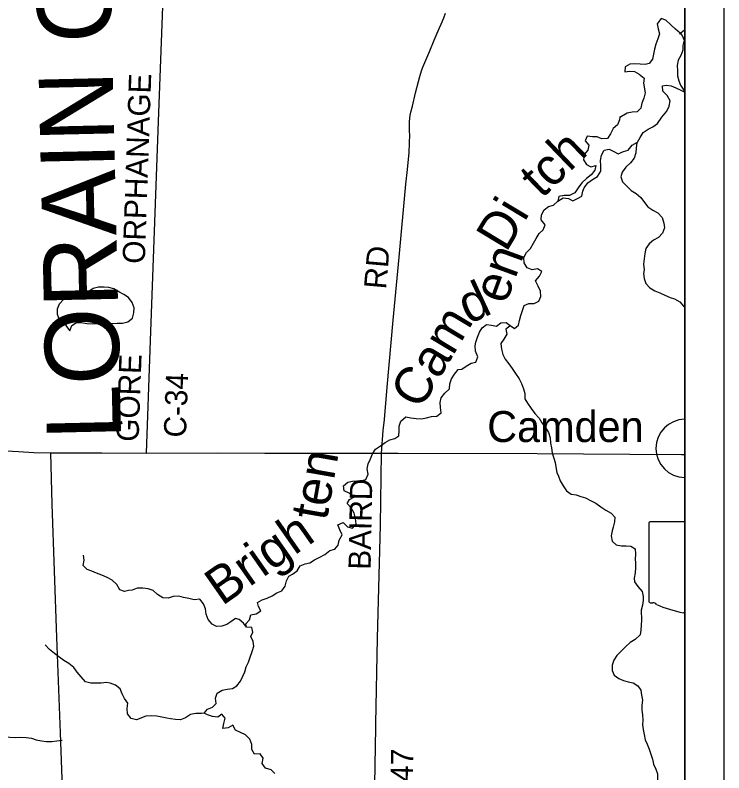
# Model space of a CAD drawing. Extents: x 0 to 34, y 0 to 22.
# Drawn here: x 7.191 to 9, y 16.386 to 18.319 of the extents above; entities that cross this region are included whole.
import ezdxf

# ---------------------------------------------------------------- set-up
doc = ezdxf.new("R2010")
doc.units = 0
for name, color, linetype in [('GM_X_Corporation', 7, 'Continuous'), ('GM_X_County_Road', 7, 'Continuous'), ('GM_X_County_Road_Text', 7, 'Continuous'), ('GM_X_County_Text', 7, 'Continuous'), ('GM_X_Minor_Lake', 7, 'Continuous'), ('GM_X_Minor_River', 7, 'Continuous'), ('GM_X_Minor_River_Text', 7, 'Continuous'), ('GM_X_State_Route', 7, 'Continuous'), ('GM_X_State_Shield', 7, 'Continuous'), ('GM_X_Township_Road', 7, 'Continuous'), ('GM_X_Township_Road_Text', 7, 'Continuous'), ('GM_X_Unincorporated', 7, 'Continuous'), ('GM_X_Unincorporated_Text', 7, 'Continuous'), ('SH_Data', 7, 'Continuous')]:
    doc.layers.add(name, color=color, linetype=linetype)

msp = doc.modelspace()

# ---------------------------------------------------------------- linework, layer by layer
at = {"layer": 'GM_X_Corporation'}
msp.add_lwpolyline([(8.9, 14.1), (8.9, 20.9), (6.9799, 20.9), (6.9799, 20.8943), (6.9814, 20.8368), (6.9837, 20.7502), (6.9864, 20.657), (6.9927, 20.4427), (6.9931, 20.4255), (6.9989, 19.9212), (7.0018, 19.871), (7.0046, 19.8599), (7.0077, 19.6756), (7.0107, 19.4664), (7.0305, 18.5559), (7.0429, 18.0629), (7.0494, 17.8247), (7.0577, 17.449), (7.0649, 17.2134), (7.0651, 17.204), (7.0717, 16.9849), (7.0838, 16.6084), (7.1072, 15.3824)], dxfattribs=at)
msp.add_lwpolyline([(8.9, 14.638), (8.9, 19.8484), (8.3424, 19.8533), (7.6795, 19.8561), (7.3272, 19.8568), (7.1717, 19.8568), (7.0046, 19.8599), (7.0077, 19.6756), (7.0107, 19.4664), (7.0305, 18.5559), (7.0429, 18.0629), (7.0494, 17.8247), (7.0577, 17.449), (7.0649, 17.2134), (7.0651, 17.204), (7.0717, 16.9849), (7.0838, 16.6084), (7.1072, 15.3824), (7.118, 14.8105), (7.1215, 14.6514), (7.384, 14.6494), (8.0793, 14.6442), (8.8452, 14.6384)], close=True, dxfattribs=at)
at = {"layer": 'GM_X_County_Road'}
for points in [[(7.5268, 17.2021), (7.5356, 17.4654), (7.5568, 18.0484), (7.58, 18.6579)], [(7.3381, 15.6814), (7.321, 16.1128), (7.3068, 16.488), (7.2978, 16.731), (7.2856, 17.0713), (7.2822, 17.2029)], [(7.2822, 17.2029), (7.4121, 17.2024), (7.5268, 17.2021)]]:
    msp.add_lwpolyline(points, dxfattribs=at)
at = {"layer": 'GM_X_Minor_Lake'}
for points in [[(8.8888, 18.2734), (8.8769, 18.2832), (8.865, 18.2944), (8.8523, 18.3064), (8.8401, 18.3105), (8.8299, 18.2971), (8.8324, 18.2845), (8.8359, 18.2717), (8.8319, 18.2587), (8.826, 18.2457), (8.8227, 18.2324), (8.8176, 18.2072), (8.809, 18.1961), (8.7995, 18.1933), (8.7862, 18.1939), (8.7725, 18.1949), (8.7603, 18.1944), (8.7483, 18.1874), (8.7469, 18.1745), (8.7594, 18.1765), (8.772, 18.1759), (8.7842, 18.1688), (8.7965, 18.1587), (8.7947, 18.1458), (8.7996, 18.1215), (8.7956, 18.1078), (8.7908, 18.0948), (8.7879, 18.0819), (8.7788, 18.0723), (8.7663, 18.0717), (8.7534, 18.0693), (8.7345, 18.0586)], [(8.8888, 18.2734), (8.8769, 18.2832), (8.865, 18.2944), (8.8523, 18.3064), (8.8401, 18.3105), (8.8299, 18.2971), (8.8324, 18.2845), (8.8359, 18.2717), (8.8319, 18.2587), (8.826, 18.2457), (8.8227, 18.2324), (8.8176, 18.2072), (8.809, 18.1961), (8.7995, 18.1933), (8.7862, 18.1939), (8.7725, 18.1949), (8.7603, 18.1944), (8.7483, 18.1874), (8.7469, 18.1745), (8.7594, 18.1765), (8.772, 18.1759), (8.7842, 18.1688), (8.7965, 18.1587), (8.7947, 18.1458), (8.7996, 18.1215), (8.7956, 18.1078), (8.7908, 18.0948), (8.7879, 18.0819), (8.7788, 18.0723), (8.7663, 18.0717), (8.7534, 18.0693), (8.7346, 18.0587)], [(8.8888, 18.2734), (8.8938, 18.2678), (8.8985, 18.2553), (8.8952, 18.2419), (8.895, 18.2298), (8.8906, 18.2164), (8.8835, 18.2042), (8.881, 18.1912), (8.8815, 18.1776), (8.8813, 18.1646), (8.8848, 18.1521), (8.8895, 18.1404), (8.8977, 18.1276), (8.9, 18.1275)], [(8.842, 18.0589), (8.8549, 18.0743), (8.8608, 18.0873), (8.8633, 18.101), (8.8552, 18.1142), (8.8444, 18.1258), (8.8431, 18.1387), (8.8526, 18.1408), (8.8652, 18.1386), (8.8774, 18.1338), (8.8904, 18.1279), (8.9, 18.1225)], [(8.7346, 18.0587), (8.7334, 18.0522), (8.7283, 18.0394), (8.7171, 18.0301), (8.7105, 18.0165), (8.7027, 18.0044), (8.689, 18.0035), (8.6765, 18.0086), (8.6647, 18.0092), (8.651, 18.0102), (8.6463, 17.9985), (8.6556, 17.9877), (8.6532, 17.9752), (8.6431, 17.9635), (8.6418, 17.9499), (8.6492, 17.938), (8.6606, 17.9325), (8.6732, 17.9361), (8.6707, 17.9239), (8.6614, 17.9123), (8.6491, 17.9026), (8.6372, 17.8914), (8.6279, 17.879), (8.6193, 17.8658), (8.6059, 17.8595), (8.5926, 17.8593), (8.5788, 17.8569), (8.5764, 17.8451), (8.5902, 17.8529), (8.6039, 17.8519), (8.6144, 17.8453), (8.6267, 17.8512), (8.6375, 17.8575), (8.6399, 17.8704)], [(8.7346, 18.0587), (8.7334, 18.0522), (8.7283, 18.0394), (8.7171, 18.0301), (8.7105, 18.0165), (8.7027, 18.0044), (8.689, 18.0035), (8.6765, 18.0086), (8.6647, 18.0092), (8.651, 18.0102), (8.6463, 17.9985), (8.6556, 17.9877), (8.6532, 17.9752), (8.6431, 17.9635), (8.6418, 17.9499), (8.6492, 17.938), (8.6606, 17.9325), (8.6732, 17.9361), (8.6707, 17.9239), (8.6614, 17.9123), (8.6491, 17.9026), (8.6372, 17.8914), (8.6279, 17.879), (8.6193, 17.8658), (8.6059, 17.8595), (8.5926, 17.8593), (8.5788, 17.8569), (8.5764, 17.8451), (8.5902, 17.8529), (8.6039, 17.8519), (8.6144, 17.8453), (8.6267, 17.8512), (8.6375, 17.8575), (8.6399, 17.8704)], [(8.6399, 17.8704), (8.6431, 17.8787), (8.6531, 17.8911), (8.6651, 17.9004), (8.6774, 17.9079), (8.6859, 17.9214), (8.6861, 17.9351), (8.6848, 17.9481), (8.688, 17.9617), (8.6943, 17.9749), (8.7073, 17.9774), (8.719, 17.9711), (8.7307, 17.9652), (8.7437, 17.9715), (8.756, 17.9751), (8.7664, 17.9875), (8.7799, 17.9949), (8.7861, 18.0074), (8.7943, 18.0198), (8.807, 18.028), (8.8189, 18.0342), (8.8308, 18.0432), (8.842, 18.0589)], [(7.4557, 17.6134), (7.4432, 17.6212), (7.4303, 17.6245), (7.4182, 17.625), (7.4044, 17.6249), (7.3907, 17.622), (7.3792, 17.6142), (7.3654, 17.6106), (7.3529, 17.612), (7.3403, 17.6083), (7.3265, 17.6021), (7.3149, 17.5935), (7.3037, 17.5823), (7.2982, 17.5694), (7.2984, 17.5561), (7.3036, 17.5431), (7.316, 17.5353), (7.3227, 17.5246), (7.3306, 17.5138)], [(7.3306, 17.5138), (7.3357, 17.5278), (7.348, 17.5348), (7.3606, 17.535), (7.3742, 17.5322), (7.3879, 17.5316), (7.4016, 17.5329), (7.4154, 17.5346), (7.4291, 17.5336), (7.4386, 17.5327), (7.4515, 17.5333), (7.4656, 17.5334), (7.4786, 17.5367), (7.4909, 17.546), (7.4945, 17.5596), (7.4947, 17.5725), (7.49, 17.5863), (7.4802, 17.5986), (7.4685, 17.6064), (7.4557, 17.6134)]]:
    msp.add_lwpolyline(points, dxfattribs=at)
at = {"layer": 'GM_X_Minor_River'}
for points in [[(8.9, 18.2814), (8.8994, 18.2809), (8.8871, 18.2707)], [(8.7778, 17.9938), (8.7766, 17.9809), (8.7753, 17.968), (8.7709, 17.9547), (8.762, 17.9423), (8.75, 17.9315), (8.7407, 17.9191), (8.7371, 17.9066), (8.7415, 17.8943), (8.7524, 17.8828), (8.7637, 17.8716), (8.7761, 17.8645), (8.7882, 17.8537), (8.7979, 17.8414), (8.8061, 17.8299), (8.819, 17.8217), (8.8314, 17.8146), (8.8427, 17.8027), (8.8471, 17.7889), (8.8488, 17.7763), (8.8436, 17.7627), (8.8328, 17.7519), (8.8206, 17.7452), (8.8094, 17.7359), (8.8005, 17.7235), (8.7984, 17.7113), (8.7963, 17.6977), (8.7946, 17.684), (8.7963, 17.6699), (8.795, 17.6604), (8.7967, 17.6471), (8.8011, 17.6345), (8.8112, 17.6233), (8.8237, 17.6159), (8.8366, 17.6111), (8.8494, 17.6045), (8.8627, 17.5993), (8.8744, 17.5953), (8.8873, 17.5875), (8.8974, 17.5767), (8.9, 17.5738)], [(8.4821, 17.553), (8.4857, 17.5659), (8.4904, 17.5787), (8.5027, 17.5835), (8.516, 17.5837), (8.5275, 17.5896), (8.5326, 17.6017), (8.5324, 17.615), (8.5261, 17.6276), (8.5195, 17.641), (8.5299, 17.6534), (8.5358, 17.6651), (8.5245, 17.6718), (8.5107, 17.6693), (8.4978, 17.6744), (8.4904, 17.6875), (8.4891, 17.7012), (8.4961, 17.7133), (8.5069, 17.7241), (8.5139, 17.7373), (8.521, 17.7498), (8.5284, 17.7626), (8.5392, 17.7715), (8.5439, 17.784), (8.5338, 17.7967), (8.5348, 17.81), (8.5414, 17.8225), (8.5529, 17.831), (8.5655, 17.8343), (8.5764, 17.8451)], [(7.7819, 16.7574), (7.7801, 16.7658), (7.7894, 16.7763), (7.793, 16.7896), (7.806, 16.7921), (7.8186, 16.7995), (7.8127, 16.8102), (7.8098, 16.8209), (7.8221, 16.8272), (7.8343, 16.8316), (7.847, 16.8378), (7.8589, 16.8449), (7.8719, 16.8508), (7.8804, 16.8624), (7.8841, 16.8761), (7.8899, 16.8881), (7.8995, 16.8929), (7.9114, 16.9011), (7.9188, 16.9143), (7.9311, 16.9195), (7.9437, 16.9219), (7.9556, 16.9297), (7.969, 16.936), (7.9817, 16.943), (7.994, 16.9531), (8.0074, 16.9567), (8.0155, 16.9669), (8.018, 16.9801), (8.0258, 16.9929), (8.0203, 17.0059), (8.0151, 17.0186), (8.0281, 17.0245), (8.0398, 17.0133), (8.0519, 17.0104), (8.0612, 17.0217), (8.0602, 17.0346), (8.0566, 17.0484), (8.0488, 17.0618), (8.0387, 17.0734), (8.0446, 17.0835), (8.0557, 17.0895), (8.044, 17.0999), (8.0312, 17.1054), (8.0294, 17.1184), (8.0402, 17.1277), (8.0521, 17.1306), (8.0616, 17.1308), (8.0719, 17.1303), (8.086, 17.1346), (8.0919, 17.1478), (8.0898, 17.1616), (8.0926, 17.1745), (8.0982, 17.1869), (8.1037, 17.1998), (8.1111, 17.2122), (8.1237, 17.2208), (8.1357, 17.2289), (8.1472, 17.2356), (8.1606, 17.2388), (8.1709, 17.2455), (8.1715, 17.2584), (8.1716, 17.2702), (8.176, 17.2835), (8.188, 17.2943), (8.2009, 17.2922), (8.2146, 17.2905), (8.2283, 17.2891), (8.2409, 17.2916), (8.2539, 17.2952), (8.2676, 17.2961), (8.2787, 17.3047), (8.2766, 17.3184), (8.2757, 17.3306), (8.2785, 17.3428), (8.2882, 17.3544), (8.3001, 17.3656), (8.3007, 17.3782), (8.3051, 17.391), (8.3125, 17.4031), (8.3218, 17.4151), (8.3313, 17.4161), (8.3421, 17.4235), (8.3547, 17.4317), (8.3666, 17.4342), (8.3721, 17.4478), (8.3658, 17.4616), (8.3649, 17.4753), (8.3669, 17.4848), (8.3709, 17.498), (8.376, 17.5105), (8.383, 17.5218), (8.3946, 17.5296), (8.4071, 17.5287), (8.4196, 17.5254), (8.4312, 17.5344), (8.4441, 17.5353), (8.4543, 17.5272), (8.466, 17.5194), (8.4756, 17.528), (8.4788, 17.5401), (8.4821, 17.553)], [(8.4548, 17.5268), (8.4539, 17.526), (8.4435, 17.5178), (8.446, 17.5052), (8.4382, 17.4924), (8.4312, 17.4811), (8.4325, 17.4674), (8.4358, 17.4537), (8.4421, 17.4418), (8.4514, 17.4295), (8.4596, 17.4176), (8.4686, 17.4049), (8.4772, 17.3915), (8.4835, 17.3792), (8.489, 17.3662), (8.4923, 17.3543), (8.4921, 17.3407), (8.4991, 17.3291), (8.5081, 17.3157), (8.5174, 17.303), (8.5283, 17.2907), (8.5358, 17.2788), (8.5447, 17.2668), (8.5522, 17.2542), (8.5569, 17.2404), (8.5575, 17.2275), (8.5604, 17.2156), (8.5621, 17.2027), (8.5694, 17.1782), (8.5715, 17.1668), (8.574, 17.1527), (8.5777, 17.1431), (8.5821, 17.1313), (8.5895, 17.1182), (8.5981, 17.1056), (8.6101, 17.097), (8.6227, 17.0953), (8.6352, 17.0913), (8.6469, 17.0877), (8.6598, 17.081), (8.673, 17.0744), (8.6858, 17.0651), (8.6987, 17.0561), (8.7123, 17.0487), (8.7216, 17.0383), (8.7211, 17.0261), (8.7179, 17.0132), (8.7151, 17.0034), (8.7126, 16.9905), (8.7147, 16.9775), (8.7248, 16.9679), (8.7385, 16.9654), (8.7503, 16.9656), (8.7625, 16.9643), (8.7738, 16.9576), (8.7744, 16.9439), (8.7738, 16.9314), (8.7741, 16.9219), (8.7743, 16.9093), (8.7733, 16.896), (8.7713, 16.8831), (8.7719, 16.8736), (8.7801, 16.8613), (8.7913, 16.8486), (8.7942, 16.836), (8.7937, 16.8261), (8.792, 16.8136), (8.7888, 16.8011), (8.7899, 16.7752), (8.789, 16.7631), (8.7885, 16.7502), (8.7868, 16.738), (8.7737, 16.726), (8.7606, 16.7186), (8.7502, 16.7085), (8.7386, 16.6969), (8.727, 16.6857), (8.7196, 16.6736), (8.7153, 16.6611), (8.7147, 16.6475), (8.7198, 16.6352), (8.7323, 16.6263), (8.7436, 16.6215), (8.7554, 16.6183), (8.7683, 16.6155), (8.7808, 16.6084), (8.7878, 16.5969), (8.7896, 16.5843), (8.7921, 16.5718), (8.7911, 16.5588), (8.7906, 16.5455), (8.7923, 16.5337), (8.7929, 16.5204), (8.7927, 16.5086), (8.7937, 16.4964), (8.7966, 16.4838), (8.7994, 16.4705), (8.8046, 16.459), (8.8097, 16.4464), (8.8138, 16.4338), (8.8181, 16.4208)], [(7.7819, 16.7574), (7.774, 16.7675), (7.7628, 16.7775), (7.7533, 16.7796), (7.7417, 16.7717), (7.7314, 16.7647), (7.7187, 16.7603), (7.705, 16.759), (7.6937, 16.7652), (7.6836, 16.7772), (7.6788, 16.791), (7.6775, 16.8047), (7.6723, 16.8173), (7.6622, 16.8289), (7.6485, 16.8272), (7.6348, 16.8312), (7.6211, 16.8337), (7.6086, 16.8365), (7.5945, 16.836), (7.5819, 16.832), (7.5682, 16.8326), (7.5542, 16.8408), (7.5437, 16.8512), (7.5305, 16.8559), (7.5168, 16.8573), (7.5031, 16.8571), (7.49, 16.852), (7.4805, 16.851), (7.4706, 16.8485), (7.4588, 16.8532), (7.4506, 16.8663), (7.439, 16.8779), (7.4265, 16.8845), (7.4125, 16.8901), (7.3989, 16.8956), (7.3868, 16.9007), (7.375, 16.9047), (7.3649, 16.9147), (7.367, 16.9284), (7.366, 16.9417)], [(7.6825, 16.5342), (7.6738, 16.5382), (7.6823, 16.5483), (7.6949, 16.5534), (7.7046, 16.5628), (7.7029, 16.5765), (7.7065, 16.589), (7.7195, 16.5972), (7.7321, 16.5996), (7.7458, 16.6009), (7.7574, 16.6076), (7.7667, 16.6196), (7.7725, 16.6325), (7.7773, 16.6438), (7.7812, 16.6563), (7.7867, 16.6684), (7.7907, 16.6813), (7.7959, 16.6952), (7.8006, 16.7089), (7.7989, 16.7214), (7.7926, 16.7341), (7.7977, 16.745), (7.7956, 16.7565), (7.7819, 16.7574)], [(7.6738, 16.5382), (7.6665, 16.5375), (7.6528, 16.5373), (7.6391, 16.5345), (7.626, 16.5267), (7.613, 16.5212), (7.6008, 16.5221), (7.5879, 16.5239), (7.5784, 16.5255), (7.5655, 16.5284), (7.5526, 16.5309), (7.5389, 16.5315), (7.5252, 16.5309), (7.5007, 16.5214), (7.487, 16.525), (7.4777, 16.5366), (7.4771, 16.5499), (7.4788, 16.5635), (7.4702, 16.5755), (7.4647, 16.5877), (7.4591, 16.6007), (7.4471, 16.6093), (7.4335, 16.6148), (7.424, 16.6169), (7.411, 16.6151), (7.398, 16.615), (7.3843, 16.6152), (7.3711, 16.6184), (7.3598, 16.6308), (7.3493, 16.6427), (7.3407, 16.655), (7.3283, 16.6651), (7.3151, 16.6729), (7.303, 16.6818), (7.2914, 16.6907), (7.2793, 16.7008), (7.2677, 16.7124)], [(7.8544, 16.3844), (7.8446, 16.3937), (7.8306, 16.3981), (7.822, 16.41), (7.8241, 16.4237), (7.8162, 16.4345), (7.8025, 16.4339), (7.7955, 16.4458), (7.7953, 16.4587), (7.7905, 16.4717), (7.7792, 16.4829), (7.7664, 16.4892), (7.7535, 16.4947), (7.7472, 16.5074), (7.7346, 16.5011), (7.7212, 16.499), (7.7237, 16.5119), (7.7273, 16.5256), (7.719, 16.5359), (7.7087, 16.5277), (7.695, 16.5298), (7.6825, 16.5342)], [(7.0874, 16.4748), (7.098, 16.4746), (7.1118, 16.4782), (7.1255, 16.4792), (7.1384, 16.4774), (7.1513, 16.478), (7.1651, 16.4782), (7.178, 16.4772), (7.1917, 16.4766), (7.2054, 16.4768), (7.2191, 16.4758), (7.2328, 16.4741), (7.2453, 16.4705), (7.2582, 16.4676), (7.2711, 16.4663), (7.2848, 16.4657), (7.2974, 16.4678), (7.3111, 16.4695)], [(8.8181, 16.4208), (8.8203, 16.4082), (8.8265, 16.3952), (8.8306, 16.3833), (8.8304, 16.3738), (8.831, 16.3601), (8.8346, 16.3471), (8.8383, 16.3338), (8.8427, 16.3215), (8.847, 16.3089), (8.8503, 16.2967), (8.8517, 16.2849), (8.8519, 16.272), (8.8513, 16.2587), (8.853, 16.2457), (8.8517, 16.2328), (8.8515, 16.2187), (8.8529, 16.2062), (8.8565, 16.1943), (8.8605, 16.1813), (8.8634, 16.1714), (8.8666, 16.1577), (8.868, 16.1443)]]:
    msp.add_lwpolyline(points, dxfattribs=at)
at = {"layer": 'GM_X_State_Route'}
for points in [[(7.0651, 17.2128), (7.1374, 17.2097), (7.1995, 17.2057), (7.2392, 17.2038), (7.2822, 17.2029)], [(7.2822, 17.2029), (7.4121, 17.2024), (7.5268, 17.2021)], [(7.5268, 17.2021), (7.7067, 17.2029), (7.8287, 17.2021), (7.9773, 17.2015), (8.0999, 17.2015), (8.1263, 17.2015), (8.1689, 17.2014), (8.5239, 17.2008), (8.7597, 17.1993), (8.8917, 17.1982), (8.9, 17.1982)]]:
    msp.add_lwpolyline(points, dxfattribs=at)
at = {"layer": 'GM_X_State_Shield'}
msp.add_line((8.8085, 17.0234), (8.8085, 16.8233), dxfattribs=at)
msp.add_lwpolyline([(8.9, 16.7939), (8.9, 17.0269), (8.8117, 17.0269)], dxfattribs=at)
for centre, major_axis, start_param, end_param in [((8.8123, 17.0238), (0.00382, 0), 1.727492, 3.291633), ((8.8123, 16.8229), (0.00385, 0), 2.993084, 4.5083), ((8.8129, 16.8433), (0.0294, 0), 4.665946, 4.897461), ((8.8189, 16.8117), (0.0106, 0), 0.519207, 1.627899), ((8.9528, 16.9915), (0.2524, 0), 4.195997, 4.488961), ((8.8775, 16.7334), (0.079, 0), 1.281959, 1.323587)]:
    msp.add_ellipse(centre, major_axis=major_axis, ratio=0.8, start_param=start_param, end_param=end_param, dxfattribs=at)
at = {"layer": 'GM_X_Township_Road'}
for points in [[(8.1972, 17.9775), (8.1975, 17.9844), (8.198, 17.9965), (8.1982, 18.0113), (8.198, 18.0248), (8.1975, 18.0376), (8.1975, 18.0475), (8.1982, 18.0565), (8.1996, 18.0645), (8.201, 18.0714), (8.2053, 18.087), (8.2133, 18.1208), (8.2204, 18.1503), (8.224, 18.1628), (8.2287, 18.177), (8.232, 18.1862), (8.2493, 18.2285), (8.2608, 18.2555), (8.2738, 18.285), (8.2783, 18.2961), (8.2857, 18.3126), (8.2894, 18.3242)], [(8.1263, 17.2015), (8.1309, 17.2594), (8.1339, 17.288), (8.1408, 17.3704), (8.1561, 17.5413), (8.1715, 17.7022), (8.1885, 17.8877), (8.1925, 17.9258), (8.1968, 17.9686), (8.1972, 17.9775)], [(8.1119, 16.5123), (8.1162, 16.73), (8.1233, 17.0183), (8.1263, 17.2015)], [(8.097, 15.6749), (8.1117, 16.5015), (8.1119, 16.5123)]]:
    msp.add_lwpolyline(points, dxfattribs=at)
at = {"layer": 'GM_X_Unincorporated'}
msp.add_line((8.9, 17.1394), (8.9, 17.2882), dxfattribs=at)
msp.add_arc((8.9012, 17.2138), 0.0744, 90.887, 269.113, dxfattribs=at)
at = {"layer": 'SH_Data'}
for p, q in [((9, 21), (9, 14)), ((8.9, 20.9), (8.9, 14.1))]:
    msp.add_line(p, q, dxfattribs=at)

# ---------------------------------------------------------------- texts
at = {"layer": 'GM_X_County_Road_Text'}
for s, rotation, p in [('ORPHANAGE', 88.0322, (7.5221, 17.6842)), ('GORE', 87.9817, (7.5062, 17.2301)), ('C-34', 87.9422, (7.6272, 17.2408))]:
    msp.add_text(s, height=0.05682, rotation=rotation, dxfattribs=at).set_placement(p)
at = {"layer": 'GM_X_County_Text'}
msp.add_text('LORAIN COUNTY', height=0.189394, rotation=91.3059, dxfattribs=at).set_placement((7.4618, 17.2371))
at = {"layer": 'GM_X_Minor_River_Text'}
for s, height, rotation, p in [('tch', 0.09475, 43.9972, (8.5353, 17.8495)), ('Di', 0.09475, 58.9972, (8.4443, 17.712)), ('en', 0.09475, 69.9969, (8.4435, 17.5788)), ('d', 0.0947, 24.9973, (8.3489, 17.5298)), ('Cam', 0.09475, 58.9976, (8.2251, 17.3098)), ('ten', 0.09475, 79.997, (7.9864, 17.0273)), ('Brigh', 0.09475, 34.9987, (7.7193, 16.8107))]:
    msp.add_text(s, height=height, rotation=rotation, dxfattribs=at).set_placement(p)
at = {"layer": 'GM_X_Township_Road_Text'}
for s, rotation, p in [('RD', 85.0293, (8.1379, 17.6187)), ('BAIRD', 88.8947, (8.0986, 16.9039)), ('T-47', 88.9383, (8.2047, 16.2908))]:
    msp.add_text(s, height=0.05682, rotation=rotation, dxfattribs=at).set_placement(p)
at = {"layer": 'GM_X_Unincorporated_Text'}
msp.add_text('Camden', height=0.07898, rotation=0, dxfattribs=at).set_placement((8.3961, 17.2301))

doc.saveas('drawing.dxf')
